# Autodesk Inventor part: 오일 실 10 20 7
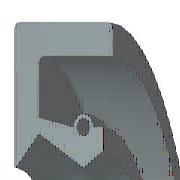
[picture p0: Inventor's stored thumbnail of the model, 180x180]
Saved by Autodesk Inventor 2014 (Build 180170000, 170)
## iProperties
IsCustomPart: 1
Created: 2012-02
Part Number: 오일 실 10 20 7
Material: 고무
Description: 오일-실
Document SubType Name: Modeling
Standard: KS B 2804
Designer: mduedu
Standards Organization: KS
Language: ko-KR
Size Designation: D - 10 20 7
Categories: <MemberInstance><Categories><Category DisplayName="샤프트 부품" InternalName="7f7aeb1f-a693-4053-b835-cee3144e0d98" Mnemonic="SHFT"><Category DisplayName="실링" Intern
Density: 0.93 g/cm^3
Mass: 1.11329 g
Surface Area: 16.3871 cm^2
Volume: 1.19708 cm^3
Appearance: 분홍색
Author: mduedu
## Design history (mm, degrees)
revolve "본체" stored, may be unused: angle "d17" = 90 deg
revolve "스프링1" stored, may be unused: angle "d18" = 90 deg
body "Solid1"
sketch "스케치1"
  geometry: L1 (0, 10)-(7, 10); L2 (7, 8.25)-(1.75, 8.25); L3 (1.75, 6.75)-(4.9, 5); L4 (4.9, 5)-(0, 5); L5 (0, 0)-(9.586, 0) reference; L6 (4.9, 5)-(6.3, 5.875); L7 (0, 18)-(0, -3) reference; L8 (-1.941, 0)-(11.507, 0) reference; L9 (4.2, 7.1)-(1.75, 7.59); L10 (1.75, 7.59)-(1.75, 8.25); L11 (0, 10)-(0, 5.088); L12 (4.9, 5)-(0, 5); L13 (1.75, 6.75)-(0.152, 5.028); L14 (7, 10)-(7, 8.25); L15 (5.6, 7.1)-(6.3, 7.1); L16 (6.3, 7.1)-(6.3, 5.875); C1 r 0.455 at (4.9, 7.1); A1 r 0.7 centre (4.9, 7.1) between (5.6, 7.1) and (4.2, 7.1); A2 r 0.088 centre (0.088, 5.088) between (0, 5.088) and (0.152, 5.028); 1 further point
  constraints: 28 end point, 5 horizontal alignment, 5 point on line, 4 point on circle, 4 vertical alignment, 3 centre point, 3 tangent, 2 collinear, 2 horizontal, 2 perpendicular, 1 coincident, 1 parallel
  dimensions: "d0" = 20 diameter of L1 L5 (= SD2); "d1" = 1.75 distance of L1.end L2.start (= SD); "d2" = 0.91 diameter of C1 (= SPDI); "d3" = 1.4 diameter of A1 (= SPDA); "d4" = 10 diameter of L3.end L5 (= NND); "d5" = 13.5 diameter of L3.start L5 (= TKDM); "d7" = 15.18 diameter of L9.end L5 (= TKDM + 0.24 x SWDT); "d8" = 1.75 distance between parallel lines of L11 L10 (= SD); "d9" = 4.9 distance from line of L11 C1.centre (= SPDST); "d10" = 14.2 diameter of C1.centre L5 (= HLDM); "d11" = 0.0875 radius of A2 (= 0.25 x LAB); "d12" = 6.3 distance between parallel lines of L11 L16 (= SDI); "d13" = 11.75 diameter of L6.end L5 (= ABDM); "d14" = 7 distance from line of L11 L1.end (= SWDT)
fillet "모깎기1" dims "d6" = 0.3 (= RR)
other parameters: "SD2" = 20 [user parameter; used in 1 equation term], "SWDT" = 7 [user parameter; used in 2 equation terms], "RR" = 0.3 [user parameter; used in 1 equation term], "SD" = 1.75 [user parameter; used in 2 equation terms], "NND" = 10 [user parameter; used in 1 equation term], "SPDA" = 1.4 [user parameter; used in 1 equation term], "SPDI" = 0.91 [user parameter; used in 1 equation term], "TKDM" = 13.5 [user parameter; used in 2 equation terms], "HLDM" = 14.2 [user parameter; used in 1 equation term], "ABDM" = 11.75 [user parameter; used in 1 equation term], "SDI" = 6.3 [user parameter; used in 1 equation term], "SPDST" = 4.9 [user parameter; used in 1 equation term], "LAB" = 0.35 [user parameter; used in 1 equation term], "d15" = 0, "d16" = 0, "d19" = 0
